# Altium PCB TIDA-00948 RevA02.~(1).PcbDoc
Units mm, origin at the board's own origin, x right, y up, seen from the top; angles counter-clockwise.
Board outline 125.73 x 87.63 mm, 2 copper layers (Top Layer, Bottom Layer), stack 1.575 mm thick; 30 components, 8 nets, 44 pads, 0 vias.
Unrouted connection lines stored in the file: 3.
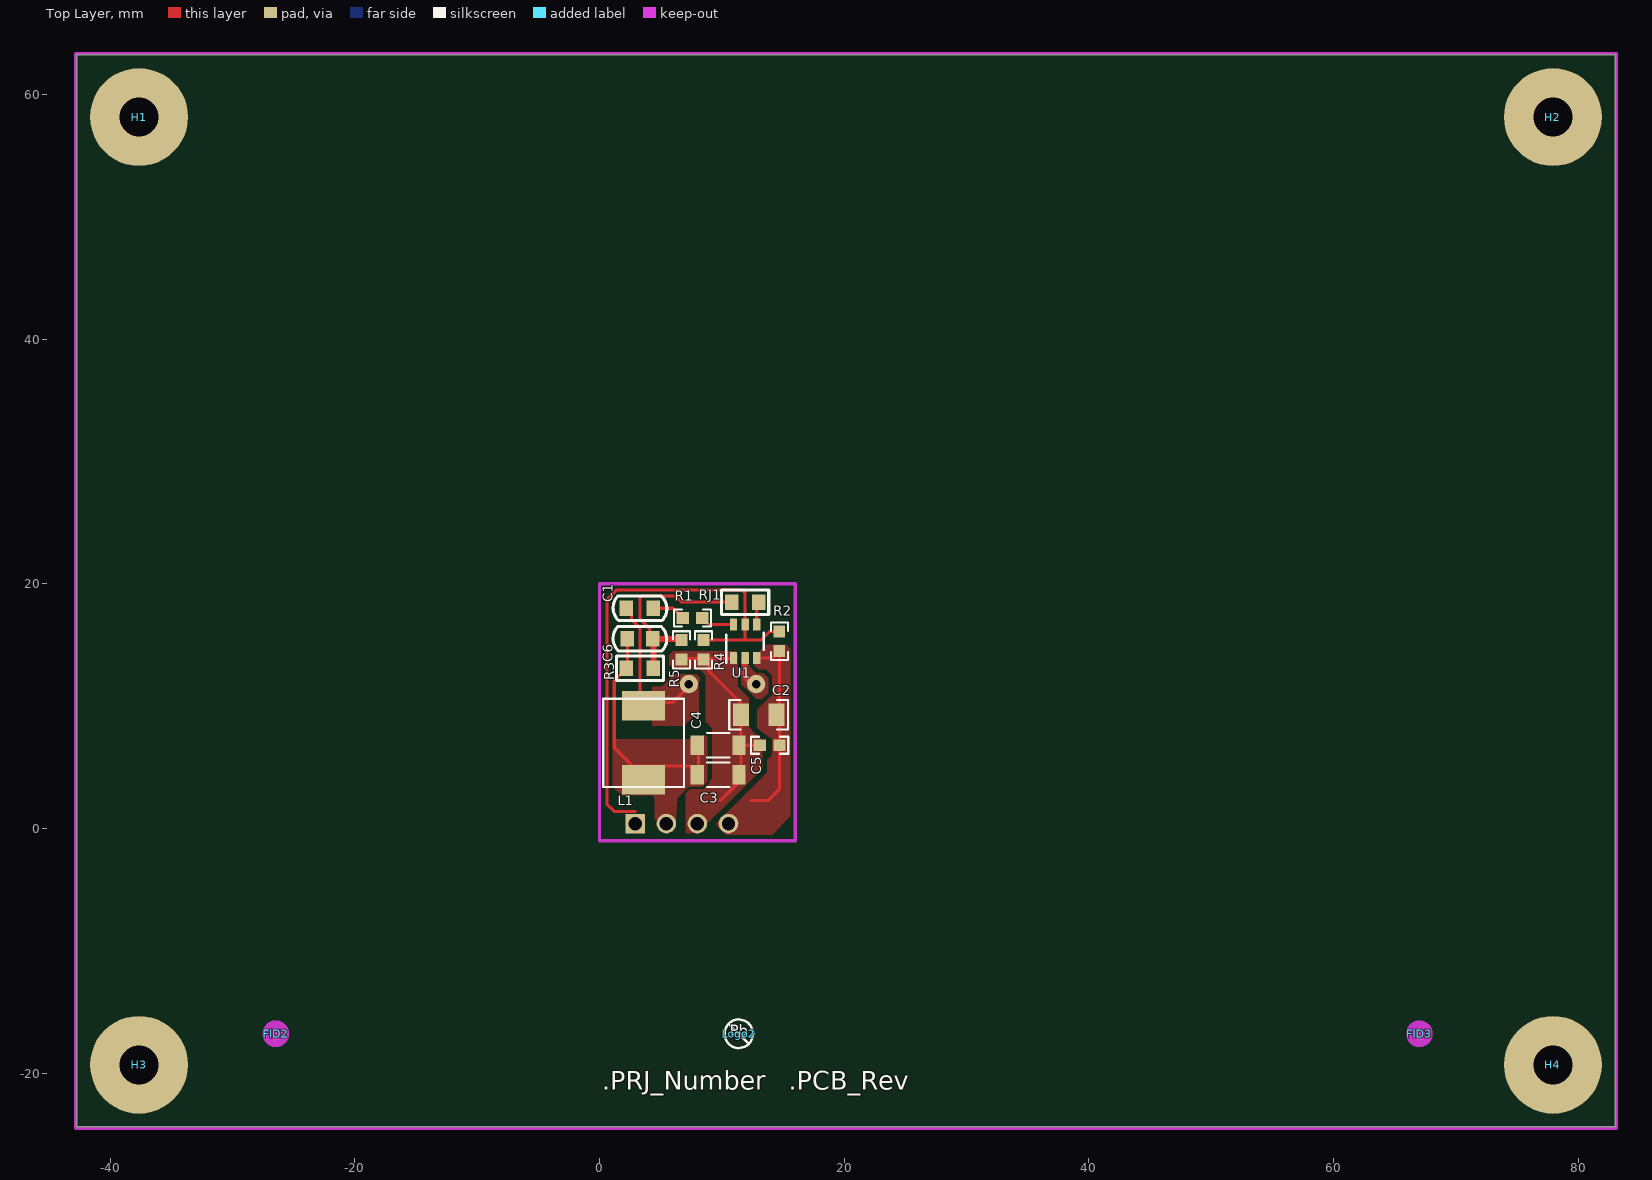
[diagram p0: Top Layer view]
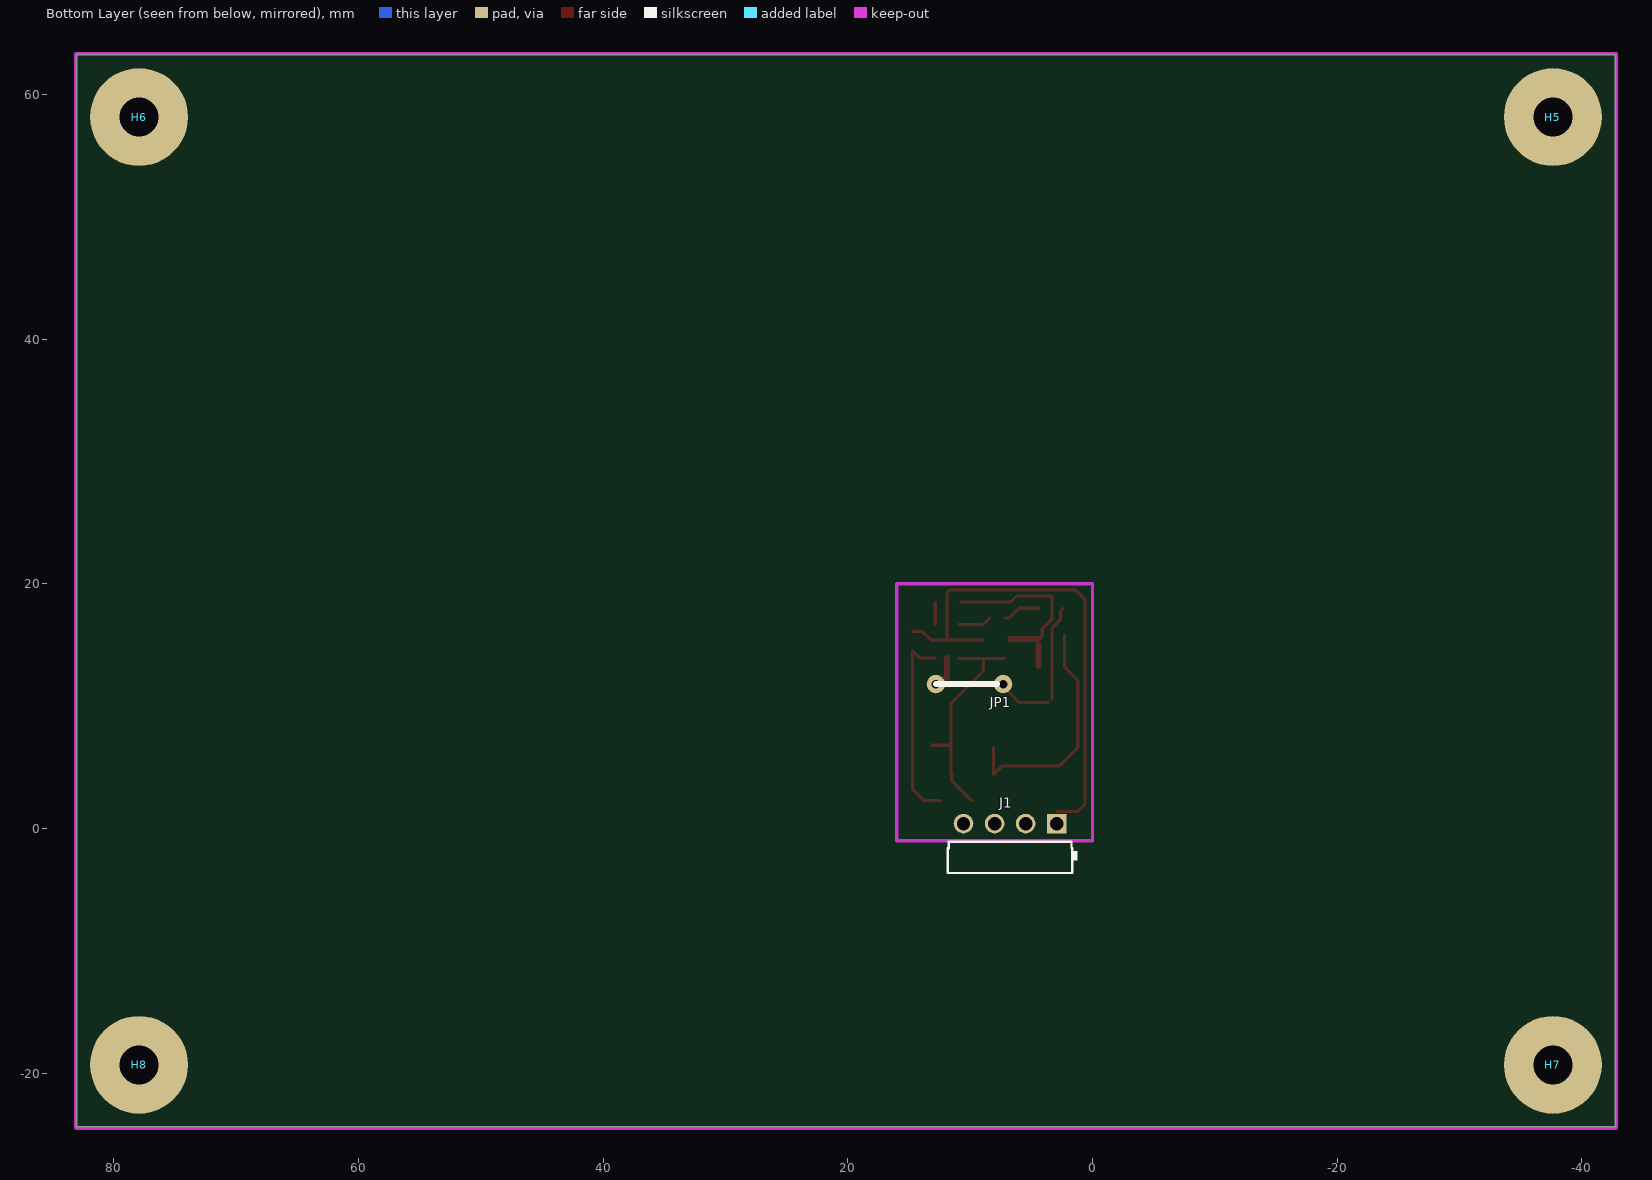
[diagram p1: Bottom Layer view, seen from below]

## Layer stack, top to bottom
Top Solder: solder mask 0.0102, Solder Resist, Dk 3.5
Top Layer: signal copper 0.0356
Dielectric1: core 1.5037, FR-4, Dk 4.8
Bottom Layer: signal copper 0.0356
Bottom Solder: solder mask 0.0102, Solder Resist, Dk 3.5

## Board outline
-42.72,-24.4 83.01,-24.4 83.01,63.23 -42.72,63.23

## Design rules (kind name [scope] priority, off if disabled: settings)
AcuteAngle [All] p1: minimum=4.50000000000000E+0001 checktracksonly=FALSE
AssemblyTestPointUsage [All] p1: valid=2
Clearance Clearance_Keepouts [((IsTrack Or IsArc) And Not InPoly) And IsFree and IsKeepOut vs ((IsTrack Or IsArc) And Not InPoly) And IsFree and IsKeepOut] p1 off: gap=0
Clearance Clearance_BoardEdge_MountingHoles [OnCopper and InComponentClass('Mounting Holes') vs IsKeepOut] p2 off: gap=1.016
Clearance Clearance_BoardEdge_Poly [OnCopper and InPoly vs IsKeepOut] p3 off: gap=0.635
Clearance Clearance_BoardEdge [OnCopper and Not InComponentClass('Logo') and not InComponentClass('FiducialMark') and not InRegion(1000,500,4000,800) and Not IsKeepout vs IsKeepOut] p4 off: gap=1.905
Clearance Clearance_Poly [InPolygon] p5 off: gap=0.635
Clearance [All] p6: gap=0.2
ComponentClearance ComponentClearance_MountingHoles_FiducialMarks [InComponentClass('Mounting Holes') vs InComponentClass('FiducialMark')] p1: gap=1.27 collisioncheckmode=3 verticalgap=0.254 showdistances=FALSE
ComponentClearance ComponentClearance_Shunt [InComponentClass('Header') vs InComponentClass('Shunt')] p2: gap=0 collisioncheckmode=3 verticalgap=0 showdistances=FALSE
ComponentClearance ComponentClearance_Logo [InComponentClass('Logo')] p3: gap=1.27 collisioncheckmode=3 verticalgap=0.254 showdistances=FALSE
ComponentClearance ComponentClearance_ScrewToNut [(HasFootprint('NY PMS 440 0025 PH')) vs (HasFootprint('Keystone_1902C'))] p4: gap=0.127 collisioncheckmode=3 verticalgap=0.254 showdistances=FALSE
ComponentClearance ComponentClearance_MountingHoles [InComponentClass('Mounting Holes')] p5: gap=6.35 collisioncheckmode=3 verticalgap=2540 showdistances=FALSE
ComponentClearance ComponentClearance_SmallPassives [HasFootprint('0201*') or HasFootprint('0402*') or HasFootprint('0508') or HasFootprint('0603*') or HasFootprint('0612') or HasFootprint('0805*') or HasFootprint('0815*') or HasFootprint('0830*') or HasFootprint('1206*') or HasFootprint('1210*') or HasFootprint('1808*') or HasFootprint('1812*') or HasFootprint('1825*') or HasFootprint('2010*') or HasFootprint('2220*') or HasFootprint('2225*') or HasFootprint('2512*') or HasFootprint('2728*') or HasFootprint('3518*') vs HasFootprint('0201*') or HasFootprint('0402*') or HasFootprint('0508') or HasFootprint('0603*') or HasFootprint('0612') or HasFootprint('0805*') or HasFootprint('0815*') or HasFootprint('0830*') or HasFootprint('1206*') or HasFootprint('1210*') or HasFootprint('1808*') or HasFootprint('1812*') or HasFootprint('1825*') or HasFootprint('2010*') or HasFootprint('2220*') or HasFootprint('2225*') or HasFootprint('2512*') or HasFootprint('2728*') or HasFootprint('3518*')] p6: gap=0.508 collisioncheckmode=3 verticalgap=0.254 showdistances=FALSE
ComponentClearance ComponentClearance_THtoSMT [IsThruComponent vs IsSMTComponent] p7: gap=2.54 collisioncheckmode=3 verticalgap=0.762 showdistances=FALSE
ComponentClearance ComponentClearance_THtoTH [IsThruComponent vs IsThruComponent] p8: gap=3 collisioncheckmode=3 verticalgap=0.762 showdistances=FALSE
ComponentClearance [All] p9: gap=1.016 collisioncheckmode=3 verticalgap=0.254 showdistances=FALSE
DiffPairsRouting [All] p1: maxlimit=2.54 minlimit=0.254 mostfreqgap=0.254 toplayer_minwidth=0.381 toplayer_maxwidth=0.381 toplayer_prefwidth=0.381 bottomlayer_minwidth=0.381 bottomlayer_maxwidth=0.381 bottomlayer_prefwidth=0.381 maxuncoupledlength=25.4
FabricationTestPointUsage TestPointUsage [All] p1: valid=2 allowmultiple=FALSE
FabricationTestpoint Testpoint [All] p1: side=3 testpointundercomponent=TRUE minsize=1.016 maxsize=2.54 preferedsize=1.524 minholesize=0 maxholesize=1.016 preferedholesize=0.813 testpointgrid=0.025 allowsidetop=TRUE allowsidebottom=TRUE usegrid=TRUE gridtolerance=0
FanoutControl Fanout_LCC [IsLCC] p1: bgadir=Out bgaviamode=Centered fanoutstyle=Auto fanoutdirection=Alternating viagrid=0.025 // Fanout_LCC (Default Rule)
FanoutControl Fanout_BGA [IsBGA] p2: bgadir=Out bgaviamode=Centered fanoutstyle=Auto fanoutdirection=Alternating viagrid=0.025 // Fanout_BGA (Default Rule)
FanoutControl Fanout_Default [All] p4: bgadir=Out bgaviamode=Centered fanoutstyle=Auto fanoutdirection=Alternating viagrid=0.025 // Fanout_Default (Default Rule)
FanoutControl Fanout_Small [(CompPinCount < 5)] p5: bgadir=Out bgaviamode=Centered fanoutstyle=Auto fanoutdirection=OutThenIn viagrid=0.025 // Fanout_Small (Default Rule)
HoleSize [All] p1: absolutevalues=TRUE maxlimit=6.375 minlimit=0.203 maxpercent=80.000 minpercent=20.000
MinimumAnnularRing MinimumAnnularRing_ThermalPadVias [IsVia and InAnyComponent] p1: minimumring=0.15
MinimumAnnularRing [All] p2: minimumring=0.229
MinimumSolderMaskSliver MinimumSolderMaskSliver_Logo [InComponentClass('Logo') vs InComponentClass('Logo')] p1: minsoldermaskwidth=0.018
MinimumSolderMaskSliver [All] p2: minsoldermaskwidth=0.1
PlaneConnect [All] p1: planeconnectstyle=Relief reliefexpansion=0.254 reliefentries=4 reliefconductorwidth=0.254 reliefairgap=0.254
PolygonConnect [All] p1: connectstyle=Direct reliefconductorwidth=0.254 reliefentries=4 polygonreliefangle="90 Angle" airgapwidth=0.254
RoutingVias ThermalPadVias [IsVia and InAnyComponent] p1: holewidth=0.2 width=0.5 viastyle="Through Hole" minholewidth=0.2 minwidth=0.5 maxholewidth=0.33 maxwidth=0.6
RoutingVias [All] p2: holewidth=0.406 width=0.864 viastyle="Through Hole" minholewidth=0.2 minwidth=0.66 maxholewidth=1.016 maxwidth=1.651
SilkToBoardRegionClearance [Not ((IsComment or IsDesignator) And (Hide <> 'False')) and not InRegion(1000,500,4000,800)] p1:
SilkToSilkClearance SilkToSilkClearance_Pb-FreeLogo [(HasFootprint('Pb-Free_Overlay_Medium') OR HasFootprint('Pb-Free_Overlay_Small')) vs (HasFootprint('Pb-Free_Overlay_Medium') OR HasFootprint('Pb-Free_Overlay_Small'))] p1: silktosilkclearance=0
SilkToSilkClearance [All] p2: silktosilkclearance=0.102
SilkToSolderMaskClearance SilkToComonentPadClearance [IsPad and InAnycomponent] p1: minsilkscreentomaskgap=0.127 clearancetoexposedcopper=TRUE
SilkToSolderMaskClearance "Silk to Solder Mask Opening" [All] p2: minsilkscreentomaskgap=0.102 clearancetoexposedcopper=FALSE
SolderMaskExpansion [All] p1: expansion=0.05
UnpouredPolygon [All] p1: allowunpoured=FALSE
Width [All] p1: maxlimit=2.54 minlimit=0.152 preferedwidth=0.254 checkconnectedcopper=TRUE
14 further rules are at their usual default settings.

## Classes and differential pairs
component class "TIDA-00948 RevA": C1 C2 C3 C4 C5 C6 JP1 L1 R1 R2 R3 R4 R5 U1
component class Header: JP1
component class AssemblyNote: ZZ2 ZZ3 ZZ4
component class FiducialMark: FID2 FID3
component class TID_Hardware: FID2 FID3 H1 H2 H3 H4 H5 H6 H7 H8 Logo2 ZZ2 ZZ3 ZZ4
component class "Mounting Holes": H1 H2 H3 H4

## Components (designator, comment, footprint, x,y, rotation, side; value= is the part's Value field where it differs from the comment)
C1 "GRM188R71E104KA01D" C/0805/SMT1#1 4.3,18 r180 top
C2 "GRM31CR71E106KA12L" 1206 13,9.3 r180 top
C3 "GCM31CR71A226KE02" 1206_190 9.7,4.4 r0 top
C4 "GCM31CR71A226KE02" 1206_190 9.7,6.8 r0 top
C5 "GRM188R71E104KA01D" 0603 13.9,6.8 r180 top
C6 "06033C101KAT2A" C/0805/SMT1#2 2.3,15.5 r0 top
FID2 "Fiducial" Fiducial10-20 -26.464,-16.78 r0 top
FID3 "Fiducial" Fiducial10-20 67.008,-16.78 r0 top
H1 "NY PMS 440 0025 PH" "NY PMS 440 0025 PH" -37.64,58.15 r0 top locked
H2 "NY PMS 440 0025 PH" "NY PMS 440 0025 PH" 77.93,58.15 r0 top locked
H3 "NY PMS 440 0025 PH" "NY PMS 440 0025 PH" -37.64,-19.32 r0 top locked
H4 "NY PMS 440 0025 PH" "NY PMS 440 0025 PH" 77.93,-19.32 r0 top locked
H5 "1902C" Keystone_1902C -37.64,58.15 r180 bottom locked
H6 "1902C" Keystone_1902C 77.93,58.15 r180 bottom locked
H7 "1902C" Keystone_1902C -37.64,-19.32 r180 bottom locked
H8 "1902C" Keystone_1902C 77.93,-19.32 r180 bottom locked
J1 "61300411021" Wurth_61300411021 6.73,0.4 r0 bottom
JP1 "Comment" JUMP-5 7.8,11.8 r0 bottom
L1 "LPS8045B-333MRB" WE-PD-M 3.6,7 r270 top
Logo2 "Pb-Free Symbol" Pb-Free_Overlay_Small 11.382,-16.78 r0 top
R1 "CRCW06030000Z0EA" 0603 7.6,17.2 r180 top
R2 "CRCW0603510KJNEA" 0603 14.7,15.3 r270 top
R3 "CRCW0603100KFKEA" R/0805/SMT1 3.3,13.1 r180 top
R4 "CRCW0603105KFKEA" 0603 8.5,14.6 r90 top
R5 "CRCW060313K3FKEA" 0603 6.7,14.6 r90 top
RJ1 "Comment" R/0805/SMT1 11.9,18.5 r0 top
U1 "TPS54202DDCR" DDC0006A_N 11.9,15.3 r90 top
ZZ2 "These assemblies are ESD sensitive, ESD precautions shall be observed." AssemblyNote -38.021,72.859 r0 top
ZZ3 "These assemblies must be clean and free from flux and all contaminants. Use of no clean flux is not acceptable." AssemblyNote -38.021,70.61 r0 top
ZZ4 "These assemblies must comply with workmanship standards IPC-A-610 Class 2, unless otherwise specified." AssemblyNote -38.021,68.361 r0 top

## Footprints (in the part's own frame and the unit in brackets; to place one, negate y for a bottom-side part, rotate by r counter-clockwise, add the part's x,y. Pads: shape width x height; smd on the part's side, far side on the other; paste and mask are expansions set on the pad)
0603 [mm] "0603 from SM-752 data"
  rect 1x0.95 smd: 1(-0.8,0) 2(0.8,0)
  silkscreen extent -1.52,-0.69 1.52,0.69, body extent -0.87,-0.47 0.87,0.47, height 1
1206 [mm] "1206 from SM-752 data"
  rect 1.3x1.85 smd: 1(-1.45,0) 2(1.45,0)
  silkscreen extent -2.4,-1.21 2.4,1.21, body extent -1.7,-0.9 1.7,0.9, height 1.35
1206_190 [mm] "1206_190"
  rect 1.1x1.6 smd: 1(-1.7,0) 2(1.7,0)
  silkscreen extent -0.9,-1 0.9,1, body extent -1.75,-0.95 1.75,0.95, height 1.9
AssemblyNote [mm] "Assembly Note"
C/0805/SMT1#1 [mm]
  rect 1.1x1.25 smd: 1(-0.1,0) 2(2.1,0)
  silkscreen extent -1.19,-1 3.19,1.01
C/0805/SMT1#2 [mm]
  rect 1.1x1.25 smd: 1(-0.05,0) 2(2.05,0)
  silkscreen extent -1.19,-1 3.19,1.01
DDC0006A_N [mm]
  rrect17% 1x0.6 smd: 1(-1.375,0.95) 2(-1.375,0) 3(-1.375,-0.95) 4(1.375,-0.95) 5(1.375,0) 6(1.375,0.95)
  silkscreen extent -1.75,-1.52 0.7,1.53, body extent -1.43,-1.48 1.43,1.49, height 0.92
Fiducial10-20 [mm]
  round 1 smd mask+0.5: 1(0,0)
  Top Layer keep-out circle w1.178: c0,0 r0.5
JUMP-5 [mm]
  round 1.5 hole 0.7: 1(-0.5,0) 2(5,0)
  silkscreen extent 0,0 5,0
Keystone_1902C [mm] "Hex Standoff, 4-40 threaded, nylon"
  body extent -3.68,-3.2 3.71,3.2, height 12.73
"NY PMS 440 0025 PH" [mm] "4-40 nylon screw and mounting hole"
  round 8 hole 3.2: 1(0,0)
  body extent -3.3,-3.3 3.3,3.3, height 2.69
Pb-Free_Overlay_Small [mm]
  silkscreen extent -1.16,-1.17 1.17,1.17
R/0805/SMT1 [mm]
  rect 1.1x1.25 smd: 1(-1.1,0) 2(1.1,0)
  silkscreen extent -1.92,-1 1.93,1
WE-PD-M [mm] "Wurth Elektronik recommended land pattern, 2008-01-04"
  rect 2.4x3.5 smd: 1(-3.035,0) 2(3.004,0)
  silkscreen extent -3.6,-3.3 3.6,3.3, body extent -3.81,-3.84 3.81,3.79, height 4.5
Wurth_61300411021 [mm] "Header, 2.54 mm, 4x1, R/A, TH"
  rect 1.6x1.6 hole 1.1: 1(-3.81,0)
  round 1.6 hole 1.1: 2(-1.27,0) 3(1.27,0) 4(3.81,0)
  silkscreen extent -5.5,1.5 5.08,4.04, body extent -5.08,-0.32 5.08,10.04, height 5.55

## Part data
C1 C5: "CAP, CERM, 0.1 μF, 25 V, +/- 10%, X7R, 0603"
C2: "CAP, CERM, 10 μF, 25 V, +/- 10%, X7R, 1206"
C3 C4: "CAP, CERM, 22 μF, 10 V, +/- 10%, X7R, AEC-Q200 Grade 1, 1206_190"
C6: "CAP, CERM, 100 pF, 25 V, +/- 10%, X7R, 0603"
FID2 FID3: "Fiducial mark.  There is nothing to buy or mount."
H1 H2 H3 H4: "Machine Screw, Round, #4-40 x 1/4, Nylon, Philips panhead"
H5 H6 H7 H8: "Standoff, Hex, 0.5\"L #4-40 Nylon"
J1: "Header, 2.54 mm, 4x1, Gold, R/A, TH"
L1: "Inductor, Shielded, Ferrite, 33 μH, 1.2 A, 0.121 ohm, SMD"
Logo2: library part Pb-Free
R1: "RES, 0, 5%, 0.1 W, 0603"
R2: "RES, 510 k, 5%, 0.1 W, 0603"
R3: "RES, 100 k, 1%, 0.1 W, 0603"
R4: "RES, 105 k, 1%, 0.1 W, 0603"
R5: "RES, 13.3 k, 1%, 0.1 W, 0603"
U1: "4.5-V TO 28-V INPUT, 2-A OUTPUT, EMI FRIENDLY SYNCHRONUOUS STEP-DOWN CONVERTOR, DDC0006A"
ZZ2 ZZ3 ZZ4: library part AssemblyNote

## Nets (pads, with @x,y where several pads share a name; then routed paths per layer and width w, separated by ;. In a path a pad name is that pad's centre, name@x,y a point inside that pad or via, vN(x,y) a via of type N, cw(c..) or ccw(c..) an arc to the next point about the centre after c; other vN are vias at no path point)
+5V: C3.1 C4.1 C6.1 J1.2 L1.2 R3.2 | length 19.7
  Top Layer w0.254: C6.1@2.278,15.8 2.278,13.178 1.2,12.1 1.2,6.6 2.703,5.096 7.404,5.096 8.1,4.4 C4.1@8.1,6.6
EN: J1.1 R2.1 R4.2 U1.5 | length 41
  Top Layer w0.254: 2.92,1.4 1.2,1.4 0.6,2 0.6,18.7 1.4,19.5 11.619,19.5 11.9,19.219 U1.5 11.9,15.5 11.8,15.4 ; R4.2@8.9,15.4 11.8,15.4 ; R2.1 13.9,16.1 13.2,15.4 11.8,15.4
GND: C2.2 C3.2 C4.2 C5.2 J1.3 R4.1 R5.1 U1.1 | length 18.6
  Top Layer w0.254: 7.2,13.9 10.925,13.9 U1.1 ; R4.1@8.9,13.8 8.9,12.9 11.55,10.25 C2.2 C4.2@11.55,6.8 ; 9.858,2.27 11.5,3.912 C3.2@11.5,4.4 ; C3.2@11.55,4.45 C4.2@11.55,6.8 ; C5.2 C4.2@11.55,6.8
NetC1_1: C1.1 R1.2 | length 3
  Top Layer w0.254: C1.1 6,18 R1.2 R1.2@7.1,17.2
NetC1_2: C1.2 JP1.1 JP1.2 L1.1 U1.2 | length 14.7
  Top Layer w0.254: C1.2@2.4,18 2.6,17.8 2.6,17.1 3.3,16.4 L1.1@3.3,10.603 ; L1.1@3.6,10.303 6.003,10.303 JP1.1@7.5,11.8
  Top Layer w0.5: U1.2 11.9,12.4 JP1.2@12.5,11.8
NetC6_2: C6.2 R3.1 R5.2 RJ1.1 RJ1.2 U1.4 | length 17.4
  Top Layer w0.254: C6.2@4.4,15.5 4.322,15.5 4.1,15.722 4.1,16.338 3.3,17.138 3.3,18.9 3.395,18.995 6.205,18.995 6.7,18.5 RJ1.1@10.778,18.5 ; U1.4 RJ1.2@12.85,18.472
  Top Layer w0.5: R3.1@4.4,13.3 C6.2@4.4,15 ; C6.2@4.4,15.5 R5.2@6.7,15.5
NetR1_1: R1.1 U1.6 | length 2.8
  Top Layer w0.254: R1.1 8.925,16.675 U1.6
VIN: C2.1 C5.1 J1.4 R2.2 U1.3 | length 16.1
  Top Layer w0.254: 12.398,2.27 13.77,2.27 14.7,3.2 C5.1 R2.2 14.125,13.925 U1.3
pads on no net: FID2.1 FID3.1 H1.1 H2.1 H3.1 H4.1

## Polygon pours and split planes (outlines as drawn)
GND on Top Layer "Top Layer-No Net" (solid, remove dead copper, pour order 2): 11.135,14.397 11.3,14.232 11.3,11.8 11.3,11.6 11.8,11.1 12.2,10.7 12.2,9.8 12.2,8.3 12.7,7.8 13.3,7.2 13.3,5.2 13.3,4.9 11.4,3 8,-0.4 7.049,-0.4 7.049,3.049 7.6,3.6 8.633,3.6 9.2,4.087 9.2,8.2 8.9,8.5 8.7,8.7 8.7,12.2 8.7,12.5 8.4,12.8 8.2,13 7,13 6.1,13 5.7,13.4 5.7,14.2 5.972,14.472 11.135,14.472
VIN on Top Layer "Top Layer-No Net 1" (solid, remove dead copper, pour order 4): 12.6,14.1 12.6,13.4 12.9,13.1 13,13 13.5,13 13.6,13 14,12.6 14.1,12.5 14.1,11.4 14.1,10.9 13.8,10.6 12.9,9.7 12.9,9 12.9,8.223 13.211,7.912 13.615,7.679 14.1,7.3 14.1,6.8 14.1,6 13.7,5.6 13.7,4.6 9.45,0.35 10.3,-0.5 14.1,-0.5 15.6,1 15.6,7.3 15.6,14.7 15.4,14.9 15.3,15 14.2,15 13.6,15 13,14.4
NetC1_2 on Top Layer "Top Layer-No Net 2" (solid, remove dead copper, pour order 6): 8.1,12 8.1,9.6 7.6,9.1 6.9,8.4 3.1,8.4 2.2,8.4 1.8,8.8 1.8,11.4 2,11.6 4.4,11.6 5.1,11.6 5.8,12.3 6.1,12.6 7.8,12.6 7.9,12.6 8.2,12.3 8.2,11.4
NetC1_2 on Top Layer "Top Layer-No Net 3" (solid, remove dead copper, pour order 8): 12.1,13.9 12.1,13.4 12.4,13.1 12.8,12.7 13.2,12.7 13.4,12.7 13.6,12.5 13.8,12.3 13.8,11.7 13.8,11.1 13.5,10.8 13.3,10.6 12.9,10.6 12.8,10.6 12.3,11.1 11.6,11.8 11.6,13 11.6,13.9
+5V on Top Layer "Top Layer-No Net 4" (solid, remove dead copper, pour order 10): 8.8,7.7 8.8,3.8 8.4,3.4 7.3,3.4 6.35,2.45 6.221,0.547 5.278,0.435 4.5,0.72 4.5,2.4 4.4,2.7 1.8,2.7 1.1,3.4 1.1,6.8 1.2,6.9 1.2,7.6 1.5,7.3 7.5,7.3
no net on Top Solder "Top Solder-No Net" (hatched 90Degree grid 0.2 track 0.203, remove dead copper): 9,12.4 10.9,12.4 11.1,12.2 11.1,11.4 11.1,8.7 10.8,8.4 9.3,8.4 9.1,8.6 8.9,8.8 8.9,11.6
VIN on Top Solder "Top Solder-No Net" (hatched 90Degree grid 0.2 track 0.203, remove dead copper): 9.8,0.5 13.7,4.4 13.7,5.2 15.3,5.2 15.5,5 15.5,1.2 14.9,0.6 13.9,-0.4 10.6,-0.4

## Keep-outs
Keep-Out Layer:
  lines w0.254: -42.847,-24.4 ccw(c-42.72,-24.4) -42.72,-24.527 ; -42.847,-24.4 ccw(c-42.72,-24.4) -42.72,-24.527 ; -42.847,-24.4 -42.847,63.23 ; -42.847,63.23 cw(c-42.72,63.23) -42.72,63.357 ; -42.847,63.23 cw(c-42.72,63.23) -42.72,63.357 ; -42.72,-24.527 83.01,-24.527 ; -42.72,63.357 83.01,63.357 ; 83.01,-24.527 ccw(c83.01,-24.4) 83.137,-24.4 ; 83.01,-24.527 ccw(c83.01,-24.4) 83.137,-24.4 ; 83.01,63.357 cw(c83.01,63.23) 83.137,63.23 ; 83.01,63.357 cw(c83.01,63.23) 83.137,63.23 ; 83.137,-24.4 83.137,63.23 ; 0,-1 0,20 16,20 16,-1 0,-1
  text ".Layer_Name" at -28.064,-46.206 h1.52

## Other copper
Top Layer:
  text ".Layer_Name" at -28.064,-46.206 h1.52
Bottom Layer:
  text ".Layer_Name" at -28.064,-46.206 h1.52

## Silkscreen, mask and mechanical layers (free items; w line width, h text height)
Top Overlay:
  text ".PRJ_Number" at 0.206,-21.352 h1.52
  text ".PCB_Rev" at 15.446,-21.352 h1.52
  text ".Layer_Name" at -28.064,-46.206 h1.52
Bottom Overlay:
  text ".Layer_Name" at -28.064,-46.206 h1.52
Top Paste:
  text ".Layer_Name" at -28.064,-46.206 h1.52
Bottom Paste:
  text ".Layer_Name" at -28.064,-46.206 h1.52
Top Solder:
  text ".Layer_Name" at -28.064,-46.206 h1.52
  text ".Layer_Name" at -28.064,-46.206 h1.52
Bottom Solder:
  text ".Layer_Name" at -28.064,-46.206 h1.52
Drill Guide:
  text ".Layer_Name" at -28.064,-46.206 h1.52
M1 Board Outline:
  the board outline again, w0.254
  text ".Layer_Name" at -28.064,-46.206 h1.52
M2 Board Dimensions:
  rectangle: -39.545,-34.56 -30.02,-31.385
  rectangle: -42.72,-31.385 -39.545,-28.21
  lines w0.178: -42.72,-31.385 -17.32,-31.385 ; -39.545,-34.56 -39.545,-28.21 ; -36.37,-34.56 -36.37,-28.21 ; -30.02,-34.56 -30.02,-28.21 ; -23.67,-34.56 -23.67,-28.21 ; -42.72,-34.56 -42.72,-28.21 -17.32,-28.21 -17.32,-34.56 -42.72,-34.56
  text ".Layer_Name" at -28.064,-46.206 h1.52
M3 3D STEP Top:
  text ".Layer_Name" at -28.064,-46.206 h1.52
M4 3D STEP Bottom:
  text ".Layer_Name" at -28.064,-46.206 h1.52
M5 Assembly Top:
  lines w0.254: -50.137,-48.026 117.503,-48.026 ; -50.137,-42.862 117.554,-42.862 ; -50.137,-37.697 -50.137,-53.191 51.59,-53.191 117.554,-53.191 117.554,-37.697 -50.124,-37.697 -50.124,-53.191 -10.106,-53.191 ; 12.474,-53.191 12.474,-37.697 ; 44.656,-42.862 44.656,-37.697 ; 65.992,-42.862 65.992,-37.697 ; 81.791,-53.356 81.791,-48.204
  text "COMPONENTS MARKED 'DNP' SHOULD NOT BE POPULATED." at -13.421,-32.49 h1.52
  text "ASSEMBLY VARIANT:" at -13.434,-35.424 h1.52
  text ".VariantName" at 12.881,-35.424 h1.52
  text "PCB VIEWED FROM TOP SIDE" at -48.524,-41.054 h1.52
  text "BOARD #:" at 14.379,-41.054 h1.52
  text ".PRJ_Number" at 28.235,-41.054 h1.52
  text "REV:" at 49.685,-41.054 h1.52
  text ".PCB_Rev" at 57.089,-41.054 h1.52
  text "SVN REV:" at 70.97,-41.054 h1.52
  text ".VersionControl_RevNumber" at 83.823,-41.054 h1.52
  text "TID #:" at 14.379,-46.219 h1.52
  text ".TID" at 28.235,-46.219 h1.52
  text "PLOT NAME =" at -48.524,-51.434 h1.52
  text ".plot_File_Name" at -28.064,-51.434 h1.52
  text "GENERATED    :" at 14.43,-51.434 h1.52
  text ".Print_Date" at 36.515,-51.434 h1.52
  text ".Print_Time" at 55.032,-51.434 h1.52
  text "TEXAS INSTRUMENTS" at 87.15,-51.434 h1.52
M6 Assembly Bottom:
  lines w0.254: -50.15,-42.874 117.541,-42.874 ; -50.099,-48.039 117.541,-48.039 ; -14.386,-53.369 -14.386,-48.217 ; 1.412,-42.874 1.412,-37.71 ; 22.748,-42.874 22.748,-37.71 ; 54.93,-53.204 54.93,-37.71 ; 77.511,-53.204 117.529,-53.204 117.529,-37.71 -50.15,-37.71 -50.15,-53.204 15.814,-53.204 117.541,-53.204 117.541,-37.71
  text "COMPONENTS MARKED 'DNP' SHOULD NOT BE POPULATED." at 112.271,-32.477 h1.52
  text ".VariantName" at 85.753,-35.424 h1.52
  text "ASSEMBLY VARIANT:" at 112.144,-35.424 h1.52
  text ".VersionControl_RevNumber" at -16.418,-41.067 h1.52
  text "SVN REV:" at -3.566,-41.067 h1.52
  text ".PCB_Rev" at 10.315,-41.067 h1.52
  text "REV:" at 17.719,-41.067 h1.52
  text ".PRJ_Number" at 39.17,-41.067 h1.52
  text "BOARD #:" at 53.025,-41.067 h1.52
  text "PCB VIEWED FROM BOTTOM SIDE" at 115.928,-41.067 h1.52
  text ".TID" at 39.17,-46.231 h1.52
  text "TID #:" at 53.025,-46.231 h1.52
  text "TEXAS INSTRUMENTS" at -19.746,-51.447 h1.52
  text ".Print_Time" at 12.373,-51.447 h1.52
  text ".Print_Date" at 30.889,-51.447 h1.52
  text "GENERATED    :" at 52.974,-51.447 h1.52
  text ".plot_File_Name" at 95.469,-51.447 h1.52
  text "PLOT NAME =" at 115.928,-51.447 h1.52
M9 Title Sheet:
  drawing of 57 lines, arcs and shapes, not listed
  text "1" at -23.928,179.727 h1.78
  text "2" at 39.462,179.727 h1.78
  text "3" at 102.691,179.727 h1.78
  text "4" at 166.36,179.727 h1.78
  text "5" at 229.835,179.727 h1.78
  text "6" at 293.462,179.727 h1.78
  text "A" at -53.299,150.695 h1.78
  text "A" at 322.621,150.695 h1.78
  text "B" at -53.299,90.243 h1.78
  text "B" at 322.621,90.243 h1.78
  text "C" at -53.299,29.918 h1.78
  text "C" at 322.621,29.918 h1.78
  text "PROJECT TITLE:" at 245.405,-17.351 h1.14
  text ".PRJ_Title" at 246.675,-20.738 h1.78
  text "DESIGNED FOR:" at 245.405,-24.997 h1.14
  text ".PRJ_Customer" at 246.675,-28.553 h1.78
  text "D" at -53.299,-30.28 h1.78
  text "D" at 322.621,-30.28 h1.78
  text "FILE NAME:" at 245.405,-32.617 h1.14
  text ".PCB_File_Name_No_Path" at 246.675,-35.665 h1.78
  text "Texas Instruments (TI) and/or its licensors do not warrant the accuracy or completeness of this specification" at 119.18,-39.776 h1.14
  text "ENGINEER:" at 245.405,-39.983 h1.14
  text "LAYOUT BY:" at 283.632,-39.983 h1.14
  text "or any information contained therein. TI and/or its licensors do not warrant that this design will meet" at 118.037,-42.637 h1.14
  text ".PRJ_Engineer" at 246.675,-43.92 h1.78
  text ".PCB_Layout" at 284.915,-43.92 h1.78
  text "the specifications, will be suitable for your application or fit for any particular purpose, or will operate in" at 118.037,-45.499 h1.14
  text ".Layer_Name" at -28.064,-46.206 h1.52
  text "ALTIUM DESIGNER VERSION:" at 283.632,-47.857 h1.14
  text "an implementation. TI and/or its licensors do not warrant that the design is production worthy. You should" at 118.037,-48.361 h1.14
  text "completely validate and test your design implementation to confirm the system functionality for your application." at 119.18,-51.222 h1.14
  text ".print_Scale" at 246.675,-51.243 h1.78
  text ".Application_BuildNumber" at 284.915,-51.243 h1.78
  text "1" at -23.928,-56.493 h1.78
  text "2" at 39.462,-56.493 h1.78
  text "3" at 102.691,-56.493 h1.78
  text "4" at 166.36,-56.493 h1.78
  text "5" at 229.835,-56.493 h1.78
  text "6" at 293.462,-56.493 h1.78
M10 Fab Notes:
  drawing of 173 lines, arcs and shapes, not listed
  text "DESIGN INFORMATION" at 271.656,133.105 h1.52
  text "MIN. TRACK WIDTH:" at 255.284,128.533 h1.52
  text "8" at 283.129,128.533 h1.52
  text "MIL" at 287.06,128.533 h1.52
  text "MIN. CLEARANCE:" at 255.284,125.181 h1.52
  text "0.2" at 281.605,125.181 h1.52
  text "mm" at 287.06,125.181 h1.52
  text "MIN. VIA PAD SIZE:" at 255.284,121.828 h1.52
  text "24" at 282.367,121.828 h1.52
  text "MIL" at 287.06,121.828 h1.52
  text "0.05mm (2MIL)" at 272.937,118.228 h1.52
  text "MINIMUM ANNULAR RING" at 246.922,118.12 h1.52
  text "EXTERNAL" at 290.921,118.12 h1.52
  text "PER" at 252.002,115.122 h1.52
  text "IPC-D-275 CLASS 2 LEVEL C" at 257.59,115.122 h1.52
  text "MIL, HOLES" at 295.391,112.27 h1.52
  text "+/-" at 285.423,112.252 h1.52
  text "+/-" at 307.114,112.252 h1.52
  text "REGISTRATION TOLERANCES:" at 246.922,112.125 h1.52
  text "METAL" at 277.396,112.125 h1.52
  text "5" at 292.032,112.125 h1.52
  text "3" at 313.19,112.125 h1.52
  text "MIL" at 316.143,112.125 h1.52
  text "+/-" at 307.114,109.255 h1.52
  text "HOLE SIZE TOLERANCE (UNLESS OTHERWISE SPECIFIED):" at 246.922,109.128 h1.52
  text "3" at 313.19,109.128 h1.52
  text "MIL" at 316.143,109.128 h1.52
  text "MATERIAL:" at 245.023,103.808 h1.52
  text "FR-4 High Tg" at 270.079,100.243 h1.52
  text "FR-408" at 255.716,100.025 h1.52
  text "OTHER" at 293.511,100.025 h1.52
  text "X" at 266.144,99.933 h1.52
  text "62 MIL (1.6mm) +/-10%" at 263.847,95.892 h1.52
  text "THICKNESS:" at 246.922,95.784 h1.52
  text "X" at 260.591,95.784 h1.52
  text "OTHER" at 296.483,95.784 h1.52
  text "TOLERANCE:" at 246.922,91.77 h1.52
  text "X" at 268.24,91.77 h1.52
  text "ANSI IPC-6012 TYPE 3 CLASS 2" at 272.989,91.77 h1.52
  text "OTHER +/-" at 272.988,87.808 h1.52
  text "BOW & TWIST:" at 246.922,83.82 h1.52
  text "X" at 268.24,83.82 h1.52
  text "ANSI IPC-6012 TYPE 3 CLASS 2" at 272.989,83.82 h1.52
  text "OTHER +/-" at 272.988,79.794 h1.52
  text "DRILLING:" at 245.023,76.276 h1.52
  text "REFERENCE:" at 246.922,73.305 h1.52
  text "X" at 263.387,73.305 h1.52
  text "AS SHOWN" at 268.137,73.305 h1.52
  text "X" at 286.272,73.305 h1.52
  text "NC_DRILL FILES" at 289.752,73.305 h1.52
  text "PTH MIN COPPER THICKNESS:" at 246.922,69.291 h1.52
  text "X" at 281.218,69.291 h1.52
  text "1MIL" at 284.698,69.291 h1.52
  text "OTHER" at 297.321,69.291 h1.52
  text "BOARD FINISH:" at 245.023,65.253 h1.52
  text "SILKSCREEN:" at 248.965,62.256 h1.52
  text "X" at 273.064,62.256 h1.52
  text "TOP" at 276.265,62.256 h1.52
  text "X" at 286.018,62.256 h1.52
  text "BOTTOM" at 289.244,62.256 h1.52
  text "SILKSCREEN COLOR:" at 248.965,58.014 h1.52
  text "X" at 273.038,58.014 h1.52
  text "WHITE" at 276.265,58.014 h1.52
  text "OTHER" at 289.244,58.014 h1.52
  text "X" at 276.366,53.97 h1.52
  text "GREEN" at 279.592,53.97 h1.52
  text "OTHER" at 295.289,53.97 h1.52
  text "SOLDER RESIST COLOR:" at 248.965,53.696 h1.52
  text "X" at 276.366,49.652 h1.52
  text "MATTE" at 279.592,49.652 h1.52
  text "SEMI-GLOSS" at 295.278,49.636 h1.52
  text "IMMERSION GOLD (ENIG)" at 271.972,44.864 h1.52
  text "ENEPIG" at 305.946,44.78 h1.52
  text "SURFACE FINISH:" at 245.023,44.755 h1.52
  text "X" at 267.224,44.755 h1.52
  text "IMM. TIN/SILVER OR EQUIV" at 253.393,40.767 h1.52
  text "OTHER" at 289.752,40.767 h1.52
  text "ARRAY/PANEL:" at 245.023,36.221 h1.52
  text "CUT AND TRIM PER M1 BOARD OUTLINE" at 271.972,36.112 h1.52
  text "N.C. ROUTE" at 271.972,32.258 h1.52
  text "X" at 289.219,32.258 h1.52
  text "V. SCORE" at 293.969,32.258 h1.52
  text "CERTIFICATION:" at 245.023,28.778 h1.52
  text "MATERIALS AND WORKMANSHIP FOR ALL PCBS" at 263.438,28.778 h1.52
  text "TO MEET OR EXCEED THE REQUIREMENTS OF:" at 263.438,26.289 h1.52
  text "X" at 253.951,22.822 h1.52
  text "ANSI IPC-A-600F CLASS ->" at 257.482,22.822 h1.52
  text "X" at 299.114,22.822 h1.52
  text "2" at 302.135,22.822 h1.52
  text "1" at 294.134,22.784 h1.52
  text "3" at 311.126,22.784 h1.52
  text "X" at 274.628,18.771 h1.52
  text "RoHS" at 278.106,18.771 h1.52
  text "OTHER" at 294.474,18.771 h1.52
  text "PER ORDER" at 304.56,18.771 h1.52
  text "ALL BOARDS MUST MEET OR EXCEED UL94-V0 REQUIREMENTS." at 245.722,14.564 h1.52
  text "PCB MUST BEAR THE UL94V-0 UL REGISTERED MATERIAL ID NUMBER" at 245.722,11.516 h1.52
  text "ADDITIONAL REQUIREMENTS:" at 245.023,7.112 h1.52
  text "MICROSECTION:" at 246.922,4.191 h1.52
  text "YES" at 269.928,4.191 h1.52
  text "REQUIRED" at 291.81,0.225 h1.52
  text "BARE BOARD ELEC. TEST:" at 246.922,0.153 h1.52
  text "NONE" at 280.088,0.153 h1.52
  text "X" at 288.584,0.153 h1.52
  text "PER ORDER" at 306.846,0.153 h1.52
  text ".Layer_Name" at -28.064,-46.206 h1.52
M11 Gerber Information:
  lines w0.254: -50.137,-48.026 117.503,-48.026 ; -50.137,-42.862 117.554,-42.862 ; -50.137,-37.697 -50.137,-53.191 51.59,-53.191 117.554,-53.191 117.554,-37.697 -50.124,-37.697 -50.124,-53.191 -10.106,-53.191 ; 12.474,-53.191 12.474,-37.697 ; 44.656,-42.862 44.656,-37.697 ; 65.992,-42.862 65.992,-37.697 ; 81.791,-53.356 81.791,-48.204
  text "ALL ARTWORK VIEWED FROM TOP SIDE" at -48.524,-41.054 h1.52
  text "BOARD #:" at 14.379,-41.054 h1.52
  text ".PRJ_Number" at 28.235,-41.054 h1.52
  text "REV:" at 49.685,-41.054 h1.52
  text ".PCB_Rev" at 57.089,-41.054 h1.52
  text "SVN REV:" at 70.97,-41.054 h1.52
  text ".VersionControl_RevNumber" at 83.823,-41.054 h1.52
  text "LAYER NAME =" at -48.524,-46.206 h1.52
  text "TID #:" at 14.379,-46.219 h1.52
  text ".TID" at 28.235,-46.219 h1.52
  text "PLOT NAME =" at -48.524,-51.434 h1.52
  text ".plot_File_Name" at -28.064,-51.434 h1.52
  text "GENERATED    :" at 14.43,-51.434 h1.52
  text ".Print_Date" at 36.515,-51.434 h1.52
  text ".Print_Time" at 55.032,-51.434 h1.52
  text "TEXAS INSTRUMENTS" at 87.15,-51.434 h1.52
M12 Stackup:
  drawing of 191 lines, arcs and shapes, not listed
  text "Layer" at 205.961,174.482 h1.52
  text "Name" at 216.372,174.482 h1.52
  text "Material" at 239.988,174.482 h1.52
  text "Thickness" at 261.826,174.482 h1.52
  text "Constant" at 278.332,174.482 h1.52
  text "Board Layer Stack" at 292.806,174.482 h1.52
  text "1" at 205.961,171.434 h1.52
  text "Top Overlay" at 216.372,171.434 h1.52
  text "2" at 205.961,168.386 h1.52
  text "Top Solder" at 216.372,168.386 h1.52
  text "Solder Resist" at 239.988,168.386 h1.52
  text "0.40mil" at 261.826,168.386 h1.52
  text "3.5" at 278.332,168.386 h1.52
  text "3" at 205.961,165.338 h1.52
  text "Top Layer" at 216.372,165.338 h1.52
  text "Copper" at 239.988,165.338 h1.52
  text "1.40mil" at 261.826,165.338 h1.52
  text "4" at 205.961,162.29 h1.52
  text "Dielectric1" at 216.372,162.29 h1.52
  text "FR-4" at 239.988,162.29 h1.52
  text "59.20mil" at 261.826,162.29 h1.52
  text "4.8" at 278.332,162.29 h1.52
  text "5" at 205.961,159.242 h1.52
  text "Bottom Layer" at 216.372,159.242 h1.52
  text "Copper" at 239.988,159.242 h1.52
  text "1.40mil" at 261.826,159.242 h1.52
  text "6" at 205.961,156.194 h1.52
  text "Bottom Solder" at 216.372,156.194 h1.52
  text "Solder Resist" at 239.988,156.194 h1.52
  text "0.40mil" at 261.826,156.194 h1.52
  text "3.5" at 278.332,156.194 h1.52
  text "7" at 205.961,153.146 h1.52
  text "Bottom Overlay" at 216.372,153.146 h1.52
  text ".Layer_Name" at -28.064,-46.206 h1.52
M13 Component Bodies Top:
  text ".Layer_Name" at -28.064,-46.206 h1.52
M14 Component Bodies Bottom:
  text ".Layer_Name" at -28.064,-46.206 h1.52
M15 Courtyards Top:
  text ".Layer_Name" at -28.064,-46.206 h1.52
M16 Courtyards Bottom:
  text ".Layer_Name" at -28.064,-46.206 h1.52
Drill Drawing:
  circle w0.025: c98.829,53.613 r0.633
  lines w0.025: 98.196,49.184 99.462,49.184 99.462,50.449 98.196,50.449 98.196,49.184 ; 98.196,58.042 99.462,58.042 98.829,56.776 98.196,58.042
  lines w0.305: 96.472,48.045 150.305,48.045 ; 96.472,59.434 150.305,59.434 ; 105.887,44.249 105.887,63.23 ; 114.958,44.249 114.958,63.23 ; 131.773,44.249 131.773,63.23 ; 138.995,44.249 138.995,63.23 ; 96.472,44.249 150.305,44.249 150.305,63.23 96.472,63.23 96.472,44.249
  text "Symbol" at 98.75,60.573 h1.83
  text "Quantity" at 107.026,60.573 h1.83
  text "Finished Hole Size" at 116.097,60.573 h1.83
  text "Plated" at 132.911,60.573 h1.83
  text "Hole Type" at 140.134,60.573 h1.83
  text "2" at 107.026,56.776 h1.52
  text "27.56mil (0.700mm)" at 116.097,56.776 h1.52
  text "PTH" at 132.911,56.776 h1.52
  text "Round" at 140.134,56.776 h1.52
  text "4" at 107.026,52.98 h1.52
  text "43.31mil (1.100mm)" at 116.097,52.98 h1.52
  text "PTH" at 132.911,52.98 h1.52
  text "Round" at 140.134,52.98 h1.52
  text "4" at 107.026,49.184 h1.52
  text "125.98mil (3.200mm)" at 116.097,49.184 h1.52
  text "PTH" at 132.911,49.184 h1.52
  text "Round" at 140.134,49.184 h1.52
  text "10 Total" at 107.026,45.388 h1.52
  text ".Layer_Name" at -28.064,-46.206 h1.52

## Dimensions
-42.72,-24.4 to 83.01,-24.4 on M2 Board Dimensions
-42.72,-24.4 to -42.72,63.23 on M2 Board Dimensions
-42.72,-34.56 to -17.32,-34.56 on M2 Board Dimensions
